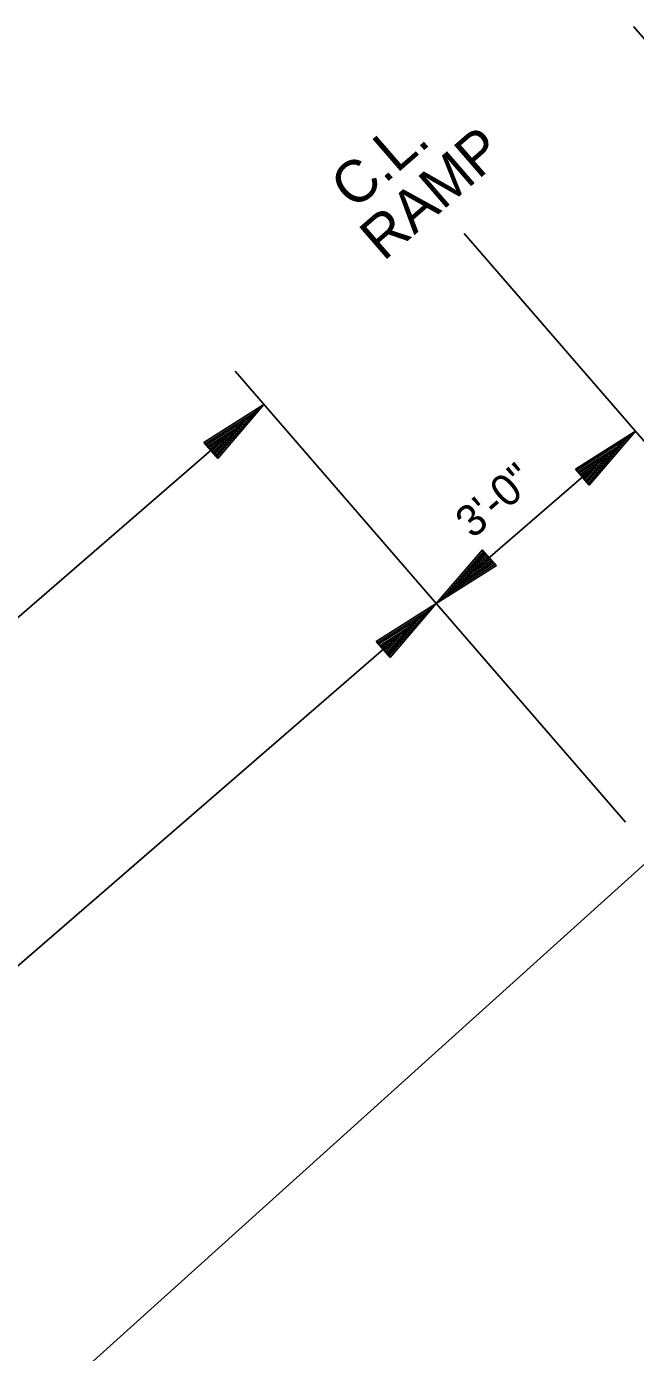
# Model space of a CAD drawing. Extents: x 192699 to 285914, y 194342 to 233219.
# Drawn here: x 262787.83 to 262794.77, y 213687.66 to 213702.77 of the extents above; entities that cross this region are included whole.
import ezdxf

# ---------------------------------------------------------------- set-up
doc = ezdxf.new("R2010")
doc.units = 0
doc.layers.add('TYPICAL SECTION FOR MOT', color=7, linetype='Continuous')

msp = doc.modelspace()

# ---------------------------------------------------------------- linework, layer by layer
at = {"layer": 'TYPICAL SECTION FOR MOT'}
for p, q in [((262799.189, 213697.631), (262794.744, 213702.765)), ((262795.278, 213697.564), (262792.816, 213700.408)), ((262794.653, 213693.704), (262790.208, 213698.838)), ((262780.706, 213689.951), (262790.535, 213698.46)), ((262789.851, 213698.027), (262790.535, 213698.46)), ((262789.865, 213698.012), (262790.434, 213698.373)), ((262789.995, 213697.861), (262790.434, 213698.373)), ((262790.009, 213697.846), (262790.535, 213698.46)), ((262789.878, 213697.997), (262790.33, 213698.283)), ((262789.891, 213697.982), (262790.229, 213698.195)), ((262789.969, 213697.891), (262790.229, 213698.195)), ((262789.982, 213697.876), (262790.33, 213698.283)), ((262789.851, 213698.027), (262790.009, 213697.846)), ((262789.905, 213697.966), (262790.127, 213698.107)), ((262789.956, 213697.907), (262790.127, 213698.107)), ((262792.498, 213696.192), (262794.767, 213698.156)), ((262794.083, 213697.723), (262794.767, 213698.156)), ((262794.096, 213697.708), (262794.666, 213698.068)), ((262794.227, 213697.556), (262794.666, 213698.068)), ((262794.24, 213697.541), (262794.767, 213698.156)), ((262789.918, 213697.951), (262790.026, 213698.019)), ((262789.942, 213697.922), (262790.026, 213698.019)), ((262794.11, 213697.692), (262794.561, 213697.978)), ((262794.123, 213697.677), (262794.461, 213697.891)), ((262794.201, 213697.587), (262794.461, 213697.891)), ((262794.214, 213697.572), (262794.561, 213697.978)), ((262794.136, 213697.661), (262794.358, 213697.802)), ((262794.187, 213697.602), (262794.358, 213697.802)), ((262794.083, 213697.723), (262794.24, 213697.541)), ((262794.149, 213697.646), (262794.257, 213697.715)), ((262794.174, 213697.618), (262794.257, 213697.715)), ((262793.025, 213696.806), (262792.498, 213696.192)), ((262793.038, 213696.791), (262792.599, 213696.279)), ((262793.051, 213696.776), (262792.703, 213696.369)), ((262793.064, 213696.761), (262792.804, 213696.457)), ((262793.142, 213696.671), (262792.804, 213696.457)), ((262793.078, 213696.745), (262792.907, 213696.545)), ((262793.129, 213696.686), (262792.907, 213696.545)), ((262793.091, 213696.73), (262793.008, 213696.633)), ((262793.116, 213696.701), (262793.008, 213696.633)), ((262793.182, 213696.625), (262793.025, 213696.806)), ((262793.182, 213696.625), (262792.498, 213696.192)), ((262793.169, 213696.64), (262792.599, 213696.279)), ((262793.155, 213696.655), (262792.703, 213696.369)), ((262781.158, 213686.374), (262792.498, 213696.192)), ((262791.815, 213695.759), (262792.498, 213696.192)), ((262791.828, 213695.744), (262792.397, 213696.105)), ((262791.959, 213695.593), (262792.397, 213696.105)), ((262791.972, 213695.578), (262792.498, 213696.192)), ((262791.841, 213695.729), (262792.293, 213696.014)), ((262791.855, 213695.713), (262792.193, 213695.927)), ((262791.933, 213695.623), (262792.193, 213695.927)), ((262791.946, 213695.608), (262792.293, 213696.014)), ((262791.868, 213695.698), (262792.09, 213695.839)), ((262791.919, 213695.639), (262792.09, 213695.839)), ((262791.815, 213695.759), (262791.972, 213695.578)), ((262791.881, 213695.683), (262791.989, 213695.751)), ((262791.906, 213695.654), (262791.989, 213695.751)), ((262797.209, 213695.334), (262783.836, 213683.281))]:
    msp.add_line(p, q, dxfattribs=at)

# ---------------------------------------------------------------- texts
for s, height, p in [('C.L.', 0.48, (262791.561, 213700.665)), ('RAMP', 0.48, (262791.896, 213700.083)), ('3\'-0"', 0.36, (262792.913, 213696.922))]:
    msp.add_text(s, height=height, rotation=40.8833, dxfattribs=at).set_placement(p)

doc.saveas('drawing.dxf')
